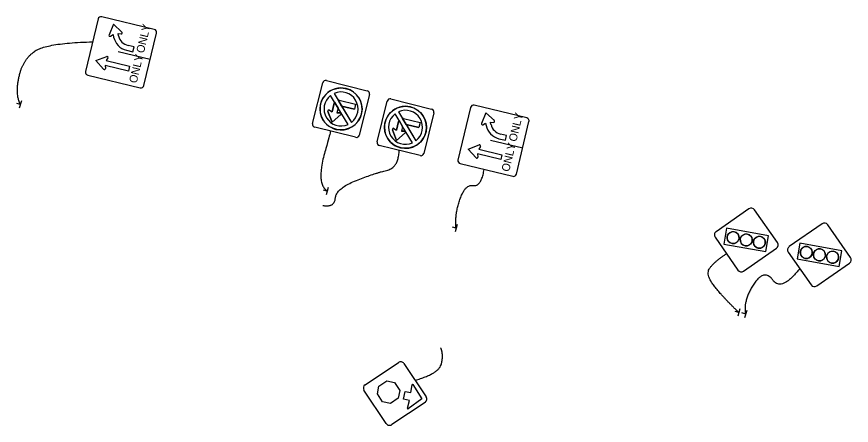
# Model space of a CAD drawing. Extents: x 1817563 to 1822411, y 498049 to 499279.
# Drawn here: x 1822063.5 to 1822411, y 498049.2 to 498219.4 of the extents above; entities that cross this region are included whole.
import ezdxf

# ---------------------------------------------------------------- set-up
doc = ezdxf.new("R2010")
doc.units = 0
doc.layers.add('PM_X_Stop_Line', color=7, linetype='Continuous')
doc.layers.add('SC_Scratch2', color=7, linetype='Continuous')

msp = doc.modelspace()

# ---------------------------------------------------------------- linework, layer by layer
at = {"layer": 'PM_X_Stop_Line'}
for p, q in [((1822103.73, 498216.31), (1822101.92, 498211.83)), ((1822107.27, 498213.01), (1822103.73, 498216.31)), ((1822102.51, 498211.31), (1822103.63, 498211.95)), ((1822103.63, 498211.95), (1822103.85, 498210.97)), ((1822105.88, 498211.41), (1822105.66, 498212.4)), ((1822105.66, 498212.4), (1822106.95, 498212.29)), ((1822112.38, 498206.84), (1822109.88, 498207.45)), ((1822111.9, 498204.82), (1822112.38, 498206.84)), ((1822096.44, 498201.14), (1822100.95, 498202.87)), ((1822105.7, 498204.91), (1822119.07, 498201.69)), ((1822109.18, 498205.47), (1822111.9, 498204.82)), ((1822099.67, 498197.54), (1822096.44, 498201.14)), ((1822101.46, 498202.27), (1822100.8, 498201.16)), ((1822100.8, 498201.16), (1822110.46, 498198.84)), ((1822109.97, 498196.81), (1822100.31, 498199.13)), ((1822100.31, 498199.13), (1822100.4, 498197.85)), ((1822110.46, 498198.84), (1822109.97, 498196.81)), ((1822195.59, 498187.45), (1822202.86, 498175.41)), ((1822065.02, 498182.85), (1822063.48, 498183.3)), ((1822065.46, 498184.39), (1822064.57, 498181.31)), ((1822195.67, 498183.42), (1822194.79, 498179.84)), ((1822197.69, 498184.63), (1822204.57, 498182.93)), ((1822198.74, 498182.23), (1822204.07, 498180.91)), ((1822204.57, 498182.93), (1822204.07, 498180.91)), ((1822193.08, 498180.01), (1822194.78, 498175.48)), ((1822193.69, 498180.51), (1822194.79, 498179.84)), ((1822198.4, 498178.69), (1822194.78, 498175.48)), ((1822197.31, 498181.37), (1822196.81, 498179.34)), ((1822198.1, 498179.42), (1822196.81, 498179.34)), ((1822258.8, 498179.44), (1822256.99, 498174.96)), ((1822262.34, 498176.14), (1822258.8, 498179.44)), ((1822257.58, 498174.44), (1822258.7, 498175.08)), ((1822258.7, 498175.08), (1822258.92, 498174.1)), ((1822260.95, 498174.53), (1822260.73, 498175.53)), ((1822260.73, 498175.53), (1822262.02, 498175.42)), ((1822260.77, 498168.03), (1822274.14, 498164.82)), ((1822264.25, 498168.6), (1822266.97, 498167.94)), ((1822267.45, 498169.97), (1822264.95, 498170.57)), ((1822266.97, 498167.94), (1822267.45, 498169.97)), ((1822251.51, 498164.26), (1822256.02, 498165.99)), ((1822256.53, 498165.39), (1822255.87, 498164.29)), ((1822254.74, 498160.67), (1822251.51, 498164.26)), ((1822265.04, 498159.94), (1822255.38, 498162.26)), ((1822255.38, 498162.26), (1822255.47, 498160.97)), ((1822255.87, 498164.29), (1822265.53, 498161.96)), ((1822265.53, 498161.96), (1822265.04, 498159.94)), ((1822192.75, 498146.78), (1822191.21, 498147.22)), ((1822193.2, 498148.31), (1822192.31, 498145.24)), ((1822246.49, 498131.37), (1822244.95, 498131.81)), ((1822246.93, 498132.91), (1822246.04, 498129.83)), ((1822366.98, 498095.58), (1822365.45, 498096.03)), ((1822367.43, 498097.12), (1822366.54, 498094.05))]:
    msp.add_line(p, q, dxfattribs=at)
for points in [[(1822097.4, 498218.48), (1822092.14, 498196.6)], [(1822120.78, 498214.14), (1822098.9, 498219.4)], [(1822116.44, 498190.75), (1822121.7, 498212.63)], [(1822093.06, 498195.09), (1822114.93, 498189.83)], [(1822192.42, 498192.81), (1822209.4, 498188.61)], [(1822186.7, 498174.91), (1822190.9, 498191.89)], [(1822195.83, 498183.82), (1822194.16, 498186.59)], [(1822195.59, 498187.45), (1822197.26, 498184.68)], [(1822210.32, 498187.09), (1822206.11, 498170.1)], [(1822193.69, 498180.51), (1822194.79, 498179.84), (1822195.67, 498183.42)], [(1822201.43, 498174.55), (1822197.31, 498181.37), (1822195.83, 498183.82)], [(1822195.83, 498183.82), (1822197.31, 498181.37), (1822196.81, 498179.34), (1822198.1, 498179.42)], [(1822197.26, 498184.68), (1822198.74, 498182.23), (1822202.86, 498175.41)], [(1822198.74, 498182.23), (1822197.26, 498184.68)], [(1822197.69, 498184.63), (1822204.57, 498182.93), (1822204.07, 498180.91), (1822198.74, 498182.23)], [(1822275.85, 498177.26), (1822253.98, 498182.53)], [(1822198.4, 498178.69), (1822194.78, 498175.48), (1822193.08, 498180.01)], [(1822252.47, 498181.6), (1822247.21, 498159.73)], [(1822271.51, 498153.88), (1822276.77, 498175.76)], [(1822204.6, 498169.19), (1822187.61, 498173.39)], [(1822248.13, 498158.22), (1822270, 498152.96)], [(1822398.81, 498133.21), (1822385.14, 498123.68)], [(1822410.66, 498119.12), (1822401.13, 498132.79)], [(1822407.03, 498121.96), (1822389.53, 498125.09), (1822388.35, 498118.52), (1822405.85, 498115.4), (1822407.03, 498121.96)], [(1822405.85, 498115.4), (1822407.03, 498121.96), (1822389.53, 498125.09), (1822388.35, 498118.52), (1822405.85, 498115.4)], [(1822384.72, 498121.36), (1822394.25, 498107.69)], [(1822396.57, 498107.27), (1822410.25, 498116.8)]]:
    msp.add_lwpolyline(points, dxfattribs=at)
for centre, radius in [((1822198.51, 498181), 8.75), ((1822392.22, 498121.22), 2.5), ((1822397.69, 498120.24), 2.5), ((1822403.16, 498119.26), 2.5)]:
    msp.add_circle(centre, radius, dxfattribs=at)
for centre, radius, start, end in [((1822098.61, 498218.18), 1.25, 76.4752, 166.4752), ((1822120.49, 498212.92), 1.25, 346.4752, 76.4752), ((1822102.3, 498211.67), 0.417, 157.9354, 299.8135), ((1822110.97, 498212.53), 7.29, 192.3901, 255.7848), ((1822110.97, 498212.53), 5.21, 192.5245, 257.9585), ((1822106.98, 498212.71), 0.417, 265.0898, 46.9679), ((1822101.1, 498202.48), 0.417, 329.1133, 110.9914), ((1822093.35, 498196.31), 1.25, 166.4752, 256.4752), ((1822099.98, 498197.82), 0.417, 221.9589, 3.837), ((1822192.12, 498191.59), 1.25, 76.1075, 166.1075), ((1822115.23, 498191.05), 1.25, 256.4752, 346.4752), ((1822198.51, 498181), 8.75, 76.1075, 256.1075), ((1822198.51, 498181), 8.75, 256.1075, 76.1075), ((1822198.51, 498181), 7.08, 127.8639, 294.3512), ((1822198.51, 498181), 7.08, 127.8639, 294.3512), ((1822198.51, 498181), 7.08, 307.8639, 114.3512), ((1822198.51, 498181), 7.08, 307.8639, 114.3512), ((1822209.1, 498187.39), 1.25, 346.1075, 76.1075), ((1822197.29, 498183.02), 1.67, 151.1075, 166.1075), ((1822197.29, 498183.02), 1.67, 151.1075, 166.1075), ((1822197.29, 498183.02), 1.67, 76.1075, 91.1075), ((1822197.29, 498183.02), 1.67, 76.1075, 91.1075), ((1822253.68, 498181.31), 1.25, 76.4752, 166.4752), ((1822193.47, 498180.15), 0.417, 58.7457, 200.6238), ((1822193.47, 498180.15), 0.417, 58.7457, 200.6238), ((1822198.12, 498179), 0.417, 311.5913, 93.4694), ((1822198.12, 498179), 0.417, 311.5913, 93.4694), ((1822187.91, 498174.61), 1.25, 166.1075, 256.1075), ((1822257.37, 498174.8), 0.417, 157.9354, 299.8135), ((1822262.05, 498175.83), 0.417, 265.0898, 46.9679), ((1822275.56, 498176.05), 1.25, 346.4752, 76.4752), ((1822266.04, 498175.66), 7.29, 192.3901, 255.7848), ((1822266.04, 498175.66), 5.21, 192.5245, 257.9585), ((1822204.9, 498170.4), 1.25, 256.1075, 346.1075), ((1822256.17, 498165.61), 0.417, 329.1133, 110.9914), ((1822255.05, 498160.95), 0.417, 221.9589, 3.837), ((1822248.42, 498159.43), 1.25, 166.4752, 256.4752), ((1822270.3, 498154.17), 1.25, 256.4752, 346.4752), ((1822399.77, 498131.84), 1.67, 34.8633, 124.8633), ((1822386.09, 498122.31), 1.67, 124.8633, 214.8633), ((1822392.22, 498121.22), 2.5, 79.8633, 259.8633), ((1822392.22, 498121.22), 2.5, 259.8633, 79.8633), ((1822397.69, 498120.24), 2.5, 79.8633, 259.8633), ((1822397.69, 498120.24), 2.5, 259.8633, 79.8633), ((1822403.16, 498119.26), 2.5, 79.8633, 259.8633), ((1822403.16, 498119.26), 2.5, 259.8633, 79.8633), ((1822409.29, 498118.17), 1.67, 304.8633, 34.8633), ((1822395.62, 498108.64), 1.67, 214.8633, 304.8633)]:
    msp.add_arc(centre, radius, start, end, dxfattribs=at)
for points in [[(1822065.02, 498182.85), (1822062.89, 498187.06), (1822065.99, 498201.58), (1822076.09, 498208.53), (1822095.1, 498208.94)], [(1822194.18, 498171.77), (1822194.18, 498171.77), (1822194.18, 498171.77), (1822188.28, 498149.91), (1822192.75, 498146.78)], [(1822246.35, 498131.49), (1822245.84, 498136.95), (1822250.23, 498149.73), (1822256.85, 498148.51), (1822258.12, 498155.82)], [(1822389.49, 498114.52), (1822381.91, 498104.74), (1822374.69, 498114.66), (1822365.97, 498101.27), (1822366.87, 498095.88)]]:
    msp.add_open_spline(points, degree=2, dxfattribs=at)
at = {"layer": 'SC_Scratch2'}
for p, q in [((1822222.43, 498179.81), (1822229.7, 498167.77)), ((1822222.51, 498175.78), (1822221.63, 498172.2)), ((1822224.53, 498177), (1822231.41, 498175.3)), ((1822231.41, 498175.3), (1822230.91, 498173.27)), ((1822219.92, 498172.37), (1822221.62, 498167.84)), ((1822220.53, 498172.87), (1822221.63, 498172.2)), ((1822224.15, 498173.73), (1822223.65, 498171.7)), ((1822224.94, 498171.78), (1822223.65, 498171.7)), ((1822225.58, 498174.59), (1822230.91, 498173.27)), ((1822225.24, 498171.05), (1822221.62, 498167.84)), ((1822364.12, 498096.27), (1822362.57, 498096.68)), ((1822364.53, 498097.81), (1822363.71, 498094.73)), ((1822214.28, 498065.54), (1822217.54, 498067.76)), ((1822217.54, 498067.76), (1822220.84, 498067.11)), ((1822213.64, 498062.31), (1822214.28, 498065.54)), ((1822220.84, 498067.11), (1822223, 498063.8)), ((1822223, 498063.8), (1822222.35, 498060.57)), ((1822227.63, 498062.84), (1822228.09, 498066.14)), ((1822228.47, 498066.22), (1822232.21, 498060.22)), ((1822215.79, 498059), (1822213.64, 498062.31)), ((1822222.35, 498060.57), (1822219.09, 498058.35)), ((1822224.53, 498060.06), (1822225.18, 498063.33)), ((1822225.18, 498063.33), (1822227.63, 498062.84)), ((1822232.21, 498060.22), (1822226.46, 498056.12)), ((1822219.09, 498058.35), (1822215.79, 498059)), ((1822226.98, 498059.57), (1822224.53, 498060.06)), ((1822226.13, 498056.34), (1822226.98, 498059.57))]:
    msp.add_line(p, q, dxfattribs=at)
for points in [[(1822213.54, 498167.27), (1822217.74, 498184.26)], [(1822219.26, 498185.17), (1822236.24, 498180.97)], [(1822222.67, 498176.18), (1822221, 498178.95)], [(1822222.43, 498179.81), (1822224.1, 498177.05)], [(1822237.16, 498179.45), (1822232.96, 498162.47)], [(1822220.53, 498172.87), (1822221.63, 498172.2), (1822222.51, 498175.78)], [(1822228.27, 498166.91), (1822224.15, 498173.73), (1822222.67, 498176.18)], [(1822222.67, 498176.18), (1822224.15, 498173.73), (1822223.65, 498171.7), (1822224.94, 498171.78)], [(1822224.1, 498177.05), (1822225.58, 498174.59), (1822229.7, 498167.77)], [(1822225.58, 498174.59), (1822224.1, 498177.05)], [(1822224.53, 498177), (1822231.41, 498175.3), (1822230.91, 498173.27), (1822225.58, 498174.59)], [(1822225.24, 498171.05), (1822221.62, 498167.84), (1822219.92, 498172.37)], [(1822231.44, 498161.55), (1822214.45, 498165.75)], [(1822368.34, 498139.41), (1822354.66, 498129.88)], [(1822380.18, 498125.32), (1822370.66, 498138.99)], [(1822376.55, 498128.16), (1822359.05, 498131.29), (1822357.88, 498124.72), (1822375.38, 498121.59), (1822376.55, 498128.16)], [(1822375.38, 498121.59), (1822376.55, 498128.16), (1822359.05, 498131.29), (1822357.88, 498124.72), (1822375.38, 498121.59)], [(1822354.25, 498127.56), (1822363.77, 498113.89)], [(1822366.09, 498113.47), (1822379.77, 498123)], [(1822208.53, 498066.15), (1822222.4, 498075.4)], [(1822224.71, 498074.94), (1822233.96, 498061.08)], [(1822217.32, 498049.97), (1822208.07, 498063.84)], [(1822233.5, 498058.76), (1822219.63, 498049.51)]]:
    msp.add_lwpolyline(points, dxfattribs=at)
for centre, radius in [((1822225.35, 498173.36), 8.75), ((1822361.75, 498127.42), 2.5), ((1822367.21, 498126.44), 2.5), ((1822372.68, 498125.46), 2.5)]:
    msp.add_circle(centre, radius, dxfattribs=at)
for centre, radius, start, end in [((1822225.35, 498173.36), 8.75, 76.1075, 256.1075), ((1822218.96, 498183.96), 1.25, 76.1075, 166.1075), ((1822225.35, 498173.36), 8.75, 256.1075, 76.1075), ((1822225.35, 498173.36), 7.08, 127.8639, 294.3512), ((1822225.35, 498173.36), 7.08, 127.8639, 294.3512), ((1822225.35, 498173.36), 7.08, 307.8639, 114.3512), ((1822225.35, 498173.36), 7.08, 307.8639, 114.3512), ((1822235.94, 498179.75), 1.25, 346.1075, 76.1075), ((1822224.13, 498175.38), 1.67, 151.1075, 166.1075), ((1822224.13, 498175.38), 1.67, 151.1075, 166.1075), ((1822224.13, 498175.38), 1.67, 76.1075, 91.1075), ((1822224.13, 498175.38), 1.67, 76.1075, 91.1075), ((1822220.31, 498172.52), 0.417, 58.7457, 200.6238), ((1822220.31, 498172.52), 0.417, 58.7457, 200.6238), ((1822224.96, 498171.36), 0.417, 311.5913, 93.4694), ((1822224.96, 498171.36), 0.417, 311.5913, 93.4694), ((1822214.75, 498166.97), 1.25, 166.1075, 256.1075), ((1822231.74, 498162.77), 1.25, 256.1075, 346.1075), ((1822369.29, 498138.04), 1.67, 34.8633, 124.8633), ((1822355.61, 498128.51), 1.67, 124.8633, 214.8633), ((1822361.75, 498127.42), 2.5, 79.8633, 259.8633), ((1822361.75, 498127.42), 2.5, 259.8633, 79.8633), ((1822367.21, 498126.44), 2.5, 79.8633, 259.8633), ((1822367.21, 498126.44), 2.5, 259.8633, 79.8633), ((1822372.68, 498125.46), 2.5, 79.8633, 259.8633), ((1822372.68, 498125.46), 2.5, 259.8633, 79.8633), ((1822378.81, 498124.37), 1.67, 304.8633, 34.8633), ((1822365.14, 498114.84), 1.67, 214.8633, 304.8633), ((1822223.32, 498074.01), 1.67, 33.7146, 123.7146), ((1822209.46, 498064.76), 1.67, 123.7146, 213.7146), ((1822228.3, 498066.11), 0.208, 31.9216, 172.1055), ((1822232.57, 498060.15), 1.67, 303.7146, 33.7146), ((1822226.34, 498056.29), 0.208, 165.3238, 305.5076), ((1822218.71, 498050.9), 1.67, 213.7146, 303.7146)]:
    msp.add_arc(centre, radius, start, end, dxfattribs=at)
for points in [[(1822190.92, 498140.83), (1822195.82, 498139.88), (1822196.5, 498147.88), (1822212.8, 498154.34), (1822222.43, 498156.55), (1822222.74, 498163.71)], [(1822364.12, 498096.27), (1822358.3, 498101.75), (1822349.97, 498112.12), (1822354.34, 498117.7), (1822359.01, 498120.72)], [(1822229.33, 498068.01), (1822239.27, 498070.8), (1822241.29, 498078.58), (1822240.05, 498081.45)]]:
    msp.add_open_spline(points, degree=2, dxfattribs=at)

# ---------------------------------------------------------------- texts
at = {"layer": 'PM_X_Stop_Line'}
for p in [(1822116.42, 498204.03), (1822113.41, 498191.52), (1822271.49, 498167.15), (1822268.48, 498154.64)]:
    msp.add_text('ONLY', height=3.333, rotation=76.4752, dxfattribs=at).set_placement(p)

doc.saveas('drawing.dxf')
